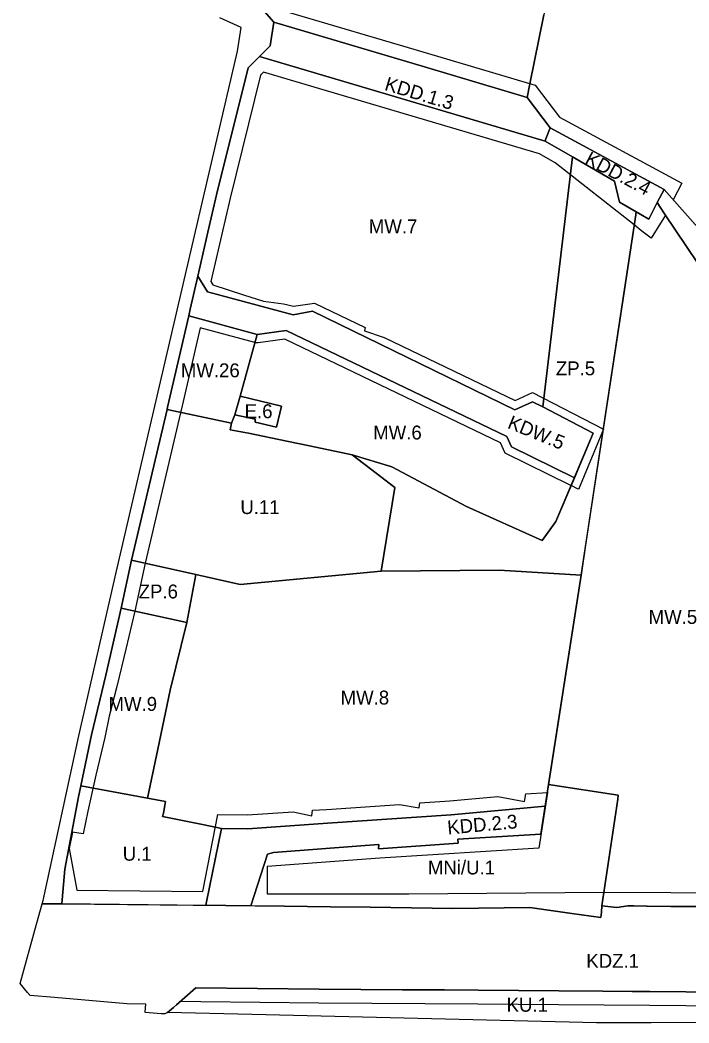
# Model space of a CAD drawing. Extents: x 7421913 to 7423341, y 5550123 to 5551175.
# Drawn here: x 7422380 to 7422620.4, y 5550123.5 to 5550484.1 of the extents above; entities that cross this region are included whole.
import ezdxf

# ---------------------------------------------------------------- set-up
doc = ezdxf.new("R2010")
doc.units = 0
for name, color, linetype in [('linie_rozgraniczajace', 7, 'Continuous'), ('linie_zabudowy_nieprzekraczalne', 7, 'Continuous'), ('oznaczenia_przeznaczen', 7, 'Continuous')]:
    doc.layers.add(name, color=color, linetype=linetype)

msp = doc.modelspace()

# ---------------------------------------------------------------- linework, layer by layer
at = {"layer": 'linie_rozgraniczajace'}
for points in [[(7422541.04, 5550581.37), (7422552.34, 5550579.58), (7422551.74, 5550577), (7422584.47, 5550571.85), (7422578.06, 5550536.87), (7422568.23, 5550485.99), (7422563.21, 5550461.08), (7422562.27, 5550456.27), (7422525.39, 5550467.23), (7422471.23, 5550483.25), (7422467.73, 5550487.22), (7422467.27, 5550489.79), (7422474.1, 5550543.35), (7422478.15, 5550575.36), (7422479.79, 5550588.35), (7422483.05, 5550589.17), (7422492.4, 5550587.95), (7422526.77, 5550583.48), (7422534.76, 5550582.37)], [(7422562.27, 5550456.27), (7422570.5, 5550445.27), (7422569.03, 5550441.37), (7422568.72, 5550440.55), (7422466.02, 5550470.94), (7422469.85, 5550474.8), (7422471.23, 5550483.25), (7422525.39, 5550467.23)], [(7422568.72, 5550440.55), (7422578.6, 5550434.85), (7422567.89, 5550345.05), (7422564.16, 5550346.84), (7422557.89, 5550343.94), (7422485.08, 5550379.35), (7422478.23, 5550378.08), (7422447.34, 5550386.32), (7422443.92, 5550391.99), (7422447.55, 5550407.77), (7422450.65, 5550421.23), (7422461.94, 5550466.83), (7422466.02, 5550470.94)], [(7422608.96, 5550418.42), (7422606.03, 5550412.53), (7422601.45, 5550415.16), (7422595.51, 5550418.57), (7422593.65, 5550426.15), (7422578.6, 5550434.85), (7422568.72, 5550440.55), (7422569.03, 5550441.37), (7422570.5, 5550445.27), (7422611.54, 5550423.13)], [(7422601.45, 5550415.16), (7422601.28, 5550414.01), (7422596.39, 5550381.72), (7422583.28, 5550295.25), (7422581.64, 5550284.47), (7422552.22, 5550286.33), (7422509.8, 5550285.93), (7422514.75, 5550315.98), (7422508.03, 5550321.14), (7422499.39, 5550327.78), (7422513.6, 5550323.37), (7422540.43, 5550309.13), (7422567.68, 5550296.95), (7422572.64, 5550303.76), (7422586.06, 5550335.55), (7422567.89, 5550345.05), (7422578.6, 5550434.85), (7422593.65, 5550426.15), (7422595.51, 5550418.57)], [(7422697.12, 5550362.91), (7422696.25, 5550358.21), (7422676.08, 5550367.3), (7422669.24, 5550370.39), (7422668.01, 5550370.94), (7422660.44, 5550374.09), (7422646.02, 5550380.62), (7422623.5, 5550396.81), (7422611.65, 5550414.43), (7422608.96, 5550418.42), (7422611.54, 5550423.13), (7422618.97, 5550414.72), (7422641.94, 5550388.78), (7422657.58, 5550379.72), (7422667.8, 5550374.88)], [(7422567.89, 5550345.05), (7422586.06, 5550335.55), (7422579.25, 5550319.43), (7422556.61, 5550330.58), (7422554.99, 5550334.3), (7422475.67, 5550372.39), (7422465.23, 5550370.97), (7422440.63, 5550377.7), (7422441.19, 5550380.16), (7422443.92, 5550391.99), (7422447.34, 5550386.32), (7422478.23, 5550378.08), (7422485.08, 5550379.35), (7422557.89, 5550343.94), (7422564.16, 5550346.84)], [(7422433.03, 5550344.87), (7422440.63, 5550377.7), (7422465.23, 5550370.97), (7422459.15, 5550348.85), (7422457.2, 5550342.11), (7422456.06, 5550339.1), (7422432.84, 5550344.01)], [(7422457.2, 5550342.11), (7422462.78, 5550340.89), (7422464.54, 5550340.52), (7422464.5, 5550339.54), (7422472.18, 5550337.75), (7422474.03, 5550345.24), (7422459.15, 5550348.85), (7422465.23, 5550370.97), (7422475.67, 5550372.39), (7422554.99, 5550334.3), (7422556.61, 5550330.58), (7422579.25, 5550319.43), (7422572.64, 5550303.76), (7422567.68, 5550296.95), (7422540.43, 5550309.13), (7422513.6, 5550323.37), (7422499.39, 5550327.78), (7422484.09, 5550330.95), (7422475.86, 5550332.66), (7422462.06, 5550335.52), (7422455.5, 5550336.76), (7422456.06, 5550339.1)], [(7422457.2, 5550342.11), (7422459.15, 5550348.85), (7422474.03, 5550345.24), (7422472.18, 5550337.75), (7422464.5, 5550339.54), (7422464.54, 5550340.52), (7422462.78, 5550340.89)], [(7422509.8, 5550285.93), (7422459.18, 5550281.12), (7422443.19, 5550284.7), (7422420.06, 5550289.86), (7422432.84, 5550344.01), (7422456.06, 5550339.1), (7422455.5, 5550336.76), (7422462.06, 5550335.52), (7422475.86, 5550332.66), (7422484.09, 5550330.95), (7422499.39, 5550327.78), (7422508.03, 5550321.14), (7422514.75, 5550315.98)], [(7422443.19, 5550284.7), (7422439.96, 5550267.44), (7422416.39, 5550272.57), (7422420.06, 5550289.86)], [(7422581.64, 5550284.47), (7422568.77, 5550201.42), (7422534.93, 5550198.36), (7422490.48, 5550195.27), (7422461.91, 5550193.28), (7422452.41, 5550193.43), (7422446.13, 5550194.67), (7422438.36, 5550196.23), (7422431.26, 5550197.66), (7422431.51, 5550198.92), (7422432.34, 5550203.06), (7422425.76, 5550204.27), (7422429.48, 5550221.9), (7422433.98, 5550243.09), (7422439.96, 5550267.44), (7422443.19, 5550284.7), (7422459.18, 5550281.12), (7422509.8, 5550285.93), (7422552.22, 5550286.33)], [(7422429.48, 5550221.9), (7422425.76, 5550204.27), (7422401.82, 5550208.77), (7422405.68, 5550227.13), (7422410.82, 5550248.48), (7422416.39, 5550272.57), (7422439.96, 5550267.44), (7422433.98, 5550243.09)], [(7422447.02, 5550166.98), (7422446.84, 5550165.77), (7422395.05, 5550166.26), (7422395.17, 5550167.77), (7422396.06, 5550178.78), (7422401.05, 5550204.74), (7422401.82, 5550208.77), (7422425.76, 5550204.27), (7422432.34, 5550203.06), (7422431.51, 5550198.92), (7422431.26, 5550197.66), (7422438.36, 5550196.23), (7422446.13, 5550194.67), (7422452.41, 5550193.43)], [(7422594.82, 5550203.91), (7422589.17, 5550165.56), (7422588.95, 5550163.31), (7422588.75, 5550161.4), (7422578.39, 5550162.88), (7422563.23, 5550165.05), (7422535.61, 5550164.62), (7422505.84, 5550165.08), (7422491.62, 5550165.25), (7422475.05, 5550165.45), (7422463.01, 5550165.59), (7422468.94, 5550184.19), (7422471.16, 5550184.76), (7422504.06, 5550187.26), (7422508.94, 5550187.63), (7422508.8, 5550186.04), (7422537.5, 5550188.18), (7422537.36, 5550189.54), (7422567.24, 5550191.34), (7422568.77, 5550201.42), (7422569.99, 5550209.26), (7422595.04, 5550205.39)], [(7422452.41, 5550193.43), (7422461.91, 5550193.28), (7422490.48, 5550195.27), (7422534.93, 5550198.36), (7422568.77, 5550201.42), (7422567.24, 5550191.34), (7422537.36, 5550189.54), (7422537.5, 5550188.18), (7422508.8, 5550186.04), (7422508.94, 5550187.63), (7422504.06, 5550187.26), (7422471.16, 5550184.76), (7422468.94, 5550184.19), (7422463.01, 5550165.59), (7422454, 5550165.7), (7422446.84, 5550165.77), (7422447.02, 5550166.98)], [(7422674.14, 5550138.95), (7422673.27, 5550124.6), (7422673.22, 5550123.8), (7422606.86, 5550123.56), (7422587.22, 5550123.49), (7422518.12, 5550125.17), (7422463.31, 5550126.5), (7422433.05, 5550127.24), (7422435.11, 5550129.05), (7422436.24, 5550130.04), (7422443.14, 5550136.08), (7422487.48, 5550135.63), (7422517.47, 5550135.44), (7422532.53, 5550135.35), (7422544.63, 5550135.28), (7422573.63, 5550135.06), (7422589.48, 5550134.93), (7422600.04, 5550134.84), (7422606.41, 5550134.79), (7422632.27, 5550134.58), (7422665, 5550136.74)]]:
    msp.add_lwpolyline(points, close=True, dxfattribs=at)
for points in [[(7422467.73, 5550487.22), (7422471.23, 5550483.25), (7422469.85, 5550474.8), (7422466.02, 5550470.94), (7422461.94, 5550466.83), (7422450.65, 5550421.23), (7422447.55, 5550407.77), (7422443.92, 5550391.99), (7422441.19, 5550380.16), (7422440.63, 5550377.7), (7422433.03, 5550344.87), (7422432.84, 5550344.01), (7422420.06, 5550289.86), (7422416.39, 5550272.57), (7422410.82, 5550248.48), (7422405.68, 5550227.13), (7422401.82, 5550208.77), (7422401.05, 5550204.74), (7422396.06, 5550178.78), (7422395.17, 5550167.77), (7422395.05, 5550166.26), (7422387.98, 5550166.33), (7422388.31, 5550167.48), (7422401.15, 5550226.76), (7422414.51, 5550285.49), (7422430.48, 5550354.01), (7422458.17, 5550472.87), (7422459.45, 5550481.38), (7422451.85, 5550484.87)], [(7422829.89, 5550383.84), (7422824.62, 5550384.35), (7422802.12, 5550385.36), (7422801.25, 5550354.66), (7422800.25, 5550321.84), (7422746.13, 5550343.06), (7422725.45, 5550351.34), (7422717.51, 5550354.58), (7422667.8, 5550374.88), (7422657.58, 5550379.72), (7422641.94, 5550388.78), (7422618.97, 5550414.72), (7422611.54, 5550423.13), (7422570.5, 5550445.27), (7422562.27, 5550456.27), (7422563.21, 5550461.08), (7422568.23, 5550485.99)], [(7422623.63, 5550165.32), (7422618.56, 5550165.36), (7422617.25, 5550165.37), (7422613.88, 5550165.41), (7422605.45, 5550165.52), (7422605.16, 5550165.53), (7422600.65, 5550165.59), (7422598.47, 5550165.57), (7422594.47, 5550165.04), (7422589.17, 5550165.56), (7422594.82, 5550203.91), (7422595.04, 5550205.39), (7422569.99, 5550209.26), (7422581.64, 5550284.47), (7422596.39, 5550381.72), (7422601.28, 5550414.01), (7422601.45, 5550415.16), (7422606.03, 5550412.53), (7422608.96, 5550418.42), (7422611.65, 5550414.43), (7422623.5, 5550396.81)], [(7422632.27, 5550134.58), (7422606.41, 5550134.79), (7422600.04, 5550134.84), (7422589.48, 5550134.93), (7422573.63, 5550135.06), (7422544.63, 5550135.28), (7422532.53, 5550135.35), (7422517.47, 5550135.44), (7422487.48, 5550135.63), (7422443.14, 5550136.08), (7422436.24, 5550130.04), (7422435.11, 5550129.05), (7422433.05, 5550127.24), (7422431.99, 5550126.82), (7422430.73, 5550126.74), (7422424.96, 5550127.21), (7422424.98, 5550127.43), (7422424.98, 5550127.44), (7422425.2, 5550130.2), (7422418.43, 5550130.34), (7422392.37, 5550132.62), (7422383.63, 5550133.38), (7422382.71, 5550134.47), (7422380.01, 5550137.65), (7422385.95, 5550159), (7422387.98, 5550166.33), (7422395.05, 5550166.26), (7422454, 5550165.7), (7422475.05, 5550165.45), (7422491.62, 5550165.25), (7422505.84, 5550165.08), (7422535.61, 5550164.62), (7422563.23, 5550165.05), (7422578.39, 5550162.88), (7422588.75, 5550161.4), (7422588.95, 5550163.31), (7422589.17, 5550165.56), (7422594.47, 5550165.04), (7422598.47, 5550165.57), (7422600.65, 5550165.59), (7422605.16, 5550165.53), (7422605.45, 5550165.52), (7422613.88, 5550165.41), (7422617.25, 5550165.37), (7422618.56, 5550165.36), (7422623.63, 5550165.32)]]:
    msp.add_lwpolyline(points, dxfattribs=at)
at = {"layer": 'linie_zabudowy_nieprzekraczalne'}
for points in [[(7422544.46, 5550580.96), (7422542.41, 5550578.12), (7422534.32, 5550579.4), (7422526.37, 5550580.51), (7422484.53, 5550585.95), (7422479.06, 5550542.72), (7422479.06, 5550542.72), (7422472.33, 5550489.92), (7422472.41, 5550489.48), (7422474.03, 5550487.64), (7422526.81, 5550472.02), (7422526.81, 5550472.02), (7422565.2, 5550460.62), (7422573.85, 5550449.15), (7422617.82, 5550425.41), (7422614.79, 5550419.46)], [(7422600.75, 5550410.49), (7422572.3, 5550432.74), (7422566.73, 5550435.93), (7422467.46, 5550465.3), (7422466.46, 5550464.29), (7422455.51, 5550420.07), (7422452.42, 5550406.65), (7422448.6, 5550390.04), (7422449.28, 5550388.91), (7422460.27, 5550385.21), (7422467.56, 5550382.95), (7422474.69, 5550382.01), (7422478.35, 5550381.15), (7422485.86, 5550382.25), (7422504.01, 5550373.48), (7422503.87, 5550372.37), (7422510.89, 5550369.92), (7422557.92, 5550347.26), (7422564.18, 5550350.17), (7422589.71, 5550337), (7422580.73, 5550315.26)], [(7422611.98, 5550413.95), (7422606.84, 5550405.7), (7422603.55, 5550408.19), (7422600.16, 5550410.92)], [(7422580.58, 5550315.4), (7422578.11, 5550316.66), (7422577.93, 5550316.74), (7422554.32, 5550328.34), (7422552.69, 5550332.07), (7422475.19, 5550369.29), (7422465.63, 5550368), (7422465.62, 5550368), (7422465.43, 5550367.98), (7422465.23, 5550367.97), (7422465.03, 5550367.98), (7422464.84, 5550368), (7422464.64, 5550368.03), (7422464.45, 5550368.07), (7422464.44, 5550368.08), (7422444.78, 5550373.45), (7422437.91, 5550343.77), (7422437.72, 5550342.93), (7422437.71, 5550342.86), (7422424.94, 5550288.77), (7422424.91, 5550288.61)], [(7422424.94, 5550288.77), (7422421.28, 5550271.53), (7422418.03, 5550257.92), (7422414.74, 5550244.5), (7422412.02, 5550233.8), (7422410.48, 5550226.11), (7422407.26, 5550212.54), (7422404.4, 5550199.61), (7422402.72, 5550191.43), (7422398.87, 5550192.13), (7422397.68, 5550186.18), (7422400.46, 5550171.21), (7422445.71, 5550170.69), (7422451.11, 5550198.43), (7422461.78, 5550198.28), (7422478.23, 5550199.43), (7422484.83, 5550198.01), (7422485.15, 5550199.95), (7422490.13, 5550200.26), (7422516.4, 5550202.05), (7422523.43, 5550200.84), (7422523.75, 5550202.62), (7422534.53, 5550203.34), (7422551.7, 5550204.93), (7422561.29, 5550203.1), (7422561.82, 5550205.82), (7422569.63, 5550206.4), (7422566.49, 5550186.37), (7422509.34, 5550182.7), (7422468.86, 5550179.71), (7422468.88, 5550169.91), (7422519.78, 5550169.85), (7422589.81, 5550170.51), (7422613.94, 5550170.41), (7422623.52, 5550170.32)], [(7422673.78, 5550133.76), (7422665.33, 5550131.75), (7422632.6, 5550129.59), (7422632.25, 5550129.58), (7422606.37, 5550129.79), (7422573.59, 5550130.06), (7422544.6, 5550130.28), (7422487.44, 5550130.63), (7422445, 5550131.06), (7422437.58, 5550131.21)]]:
    msp.add_lwpolyline(points, dxfattribs=at)

# ---------------------------------------------------------------- texts
at = {"layer": 'oznaczenia_przeznaczen'}
for s, rotation, p in [('KDD.1.3', 343.2287, (7422510.71, 5550458.98)), ('KDD.2.4', 332.072, (7422582.67, 5550432.64)), ('KDW.5', 337.851, (7422554.88, 5550337.47)), ('KDD.2.3', 5.2222, (7422533.8, 5550191.22))]:
    msp.add_text(s, height=5, rotation=rotation, dxfattribs=at).set_placement(p)
for s, p in [('MW.7', (7422505.35, 5550407.37)), ('MW.26', (7422437.79, 5550355.62)), ('ZP.5', (7422572.6, 5550356.34)), ('E.6', (7422460.72, 5550340.92)), ('MW.6', (7422506.93, 5550333.26)), ('U.11', (7422459.19, 5550306.44)), ('ZP.6', (7422422.63, 5550276.12)), ('MW.5', (7422605.94, 5550266.96)), ('MW.8', (7422495.21, 5550237.96)), ('MW.9', (7422411.8, 5550235.69)), ('U.1', (7422416.91, 5550181.82)), ('MNi/U.1', (7422526.59, 5550176.88)), ('KDZ.1', (7422583.53, 5550143.31)), ('KU.1', (7422554.88, 5550127.52))]:
    msp.add_text(s, height=5, dxfattribs=at).set_placement(p)

doc.saveas('drawing.dxf')
